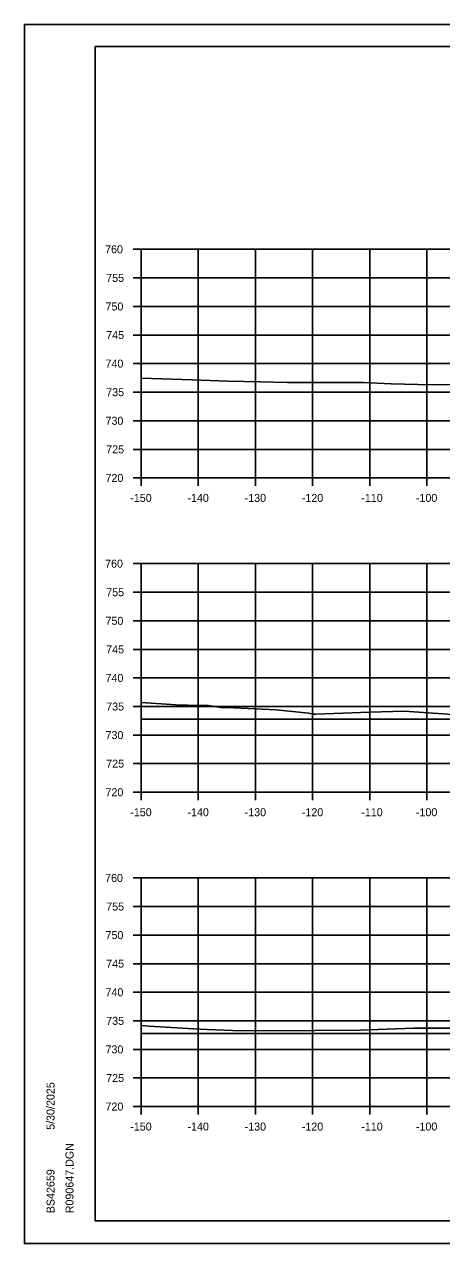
# Model space of a CAD drawing. Extents: x 1202951 to 1376887, y 378065 to 728038.
# Drawn here: x 1372926.7 to 1372999.7, y 380735.8 to 380949.1 of the extents above; entities that cross this region are included whole.
import ezdxf

# ---------------------------------------------------------------- set-up
doc = ezdxf.new("R2010")
doc.units = 0
for name, color, linetype in [('Default', 7, 'Continuous'), ('R_Axis', 7, 'Continuous'), ('R_Axis Annot', 7, 'Continuous'), ('R_Detour Annot', 7, 'Continuous'), ('R_Exist Surface', 7, 'Continuous'), ('R_Grid', 7, 'Continuous'), ('R_No Plot', 7, 'Continuous')]:
    doc.layers.add(name, color=color, linetype=linetype)

msp = doc.modelspace()

# ---------------------------------------------------------------- linework, layer by layer
at = {"layer": 'Default'}
msp.add_line((1372947.13, 380827.54), (1373247.13, 380827.54), dxfattribs=at)
at = {"layer": 'R_Axis'}
for p, q in [((1372945.73, 380909.74), (1372947.13, 380909.74)), ((1372947.13, 380869.74), (1372947.13, 380909.74)), ((1372945.73, 380904.74), (1372947.13, 380904.74)), ((1372945.73, 380899.74), (1372947.13, 380899.74)), ((1372945.73, 380894.74), (1372947.13, 380894.74)), ((1372945.73, 380889.74), (1372947.13, 380889.74)), ((1372945.73, 380884.74), (1372947.13, 380884.74)), ((1372945.73, 380879.74), (1372947.13, 380879.74)), ((1372945.73, 380874.74), (1372947.13, 380874.74)), ((1372945.73, 380869.74), (1372947.13, 380869.74)), ((1372947.13, 380869.74), (1373247.13, 380869.74)), ((1372947.13, 380868.34), (1372947.13, 380869.74)), ((1372957.13, 380868.34), (1372957.13, 380869.74)), ((1372967.13, 380868.34), (1372967.13, 380869.74)), ((1372977.13, 380868.34), (1372977.13, 380869.74)), ((1372987.13, 380868.34), (1372987.13, 380869.74)), ((1372997.13, 380868.34), (1372997.13, 380869.74)), ((1372945.73, 380854.74), (1372947.13, 380854.74)), ((1372947.13, 380814.74), (1372947.13, 380854.74)), ((1372945.73, 380849.74), (1372947.13, 380849.74)), ((1372945.73, 380844.74), (1372947.13, 380844.74)), ((1372945.73, 380839.74), (1372947.13, 380839.74)), ((1372945.73, 380834.74), (1372947.13, 380834.74)), ((1372945.73, 380829.74), (1372947.13, 380829.74)), ((1372945.73, 380824.74), (1372947.13, 380824.74)), ((1372945.73, 380819.74), (1372947.13, 380819.74)), ((1372945.73, 380814.74), (1372947.13, 380814.74)), ((1372947.13, 380814.74), (1373247.13, 380814.74)), ((1372947.13, 380813.34), (1372947.13, 380814.74)), ((1372957.13, 380813.34), (1372957.13, 380814.74)), ((1372967.13, 380813.34), (1372967.13, 380814.74)), ((1372977.13, 380813.34), (1372977.13, 380814.74)), ((1372987.13, 380813.34), (1372987.13, 380814.74)), ((1372997.13, 380813.34), (1372997.13, 380814.74)), ((1372945.73, 380799.74), (1372947.13, 380799.74)), ((1372947.13, 380759.74), (1372947.13, 380799.74)), ((1372945.73, 380794.74), (1372947.13, 380794.74)), ((1372945.73, 380789.74), (1372947.13, 380789.74)), ((1372945.73, 380784.74), (1372947.13, 380784.74)), ((1372945.73, 380779.74), (1372947.13, 380779.74)), ((1372945.73, 380774.74), (1372947.13, 380774.74)), ((1372945.73, 380769.74), (1372947.13, 380769.74)), ((1372945.73, 380764.74), (1372947.13, 380764.74)), ((1372945.73, 380759.74), (1372947.13, 380759.74)), ((1372947.13, 380759.74), (1373247.13, 380759.74)), ((1372947.13, 380758.34), (1372947.13, 380759.74)), ((1372957.13, 380758.34), (1372957.13, 380759.74)), ((1372967.13, 380758.34), (1372967.13, 380759.74)), ((1372977.13, 380758.34), (1372977.13, 380759.74)), ((1372987.13, 380758.34), (1372987.13, 380759.74)), ((1372997.13, 380758.34), (1372997.13, 380759.74))]:
    msp.add_line(p, q, dxfattribs=at)
at = {"layer": 'R_Detour Annot'}
msp.add_line((1372947.13, 380772.54), (1373004.99, 380772.54), dxfattribs=at)
at = {"layer": 'R_Exist Surface'}
for points in [[(1372947.13, 380887.19), (1372956.12, 380886.91), (1372962.26, 380886.65), (1372967.87, 380886.58), (1372972.71, 380886.46), (1372973.01, 380886.46), (1372975.18, 380886.46), (1372986.01, 380886.42), (1372990.89, 380886.23), (1372995.51, 380886.1), (1373007.53, 380886.01)], [(1372947.13, 380830.45), (1372953.29, 380830.02), (1372957.46, 380829.89), (1372958.55, 380829.98), (1372961.07, 380829.56), (1372963.42, 380829.51), (1372970.73, 380829.14), (1372976.48, 380828.56), (1372977.2, 380828.42), (1372977.67, 380828.42), (1372987.12, 380828.75), (1372993.15, 380828.93), (1373002.48, 380828.31)], [(1372947.13, 380773.9), (1372948.51, 380773.82), (1372949.49, 380773.75), (1372956.29, 380773.36), (1372958.71, 380773.2), (1372964.59, 380772.98), (1372977.51, 380773.04), (1372985.49, 380773.13), (1372994.85, 380773.48), (1373013.61, 380773.45)]]:
    msp.add_lwpolyline(points, dxfattribs=at)
at = {"layer": 'R_Grid'}
for p, q in [((1372947.13, 380909.74), (1373247.13, 380909.74)), ((1372947.13, 380869.74), (1372947.13, 380909.74)), ((1372957.13, 380869.74), (1372957.13, 380909.74)), ((1372967.13, 380869.74), (1372967.13, 380909.74)), ((1372977.13, 380869.74), (1372977.13, 380909.74)), ((1372987.13, 380869.74), (1372987.13, 380909.74)), ((1372997.13, 380869.74), (1372997.13, 380909.74)), ((1372947.13, 380904.74), (1373247.13, 380904.74)), ((1372947.13, 380899.74), (1373247.13, 380899.74)), ((1372947.13, 380894.74), (1373247.13, 380894.74)), ((1372947.13, 380889.74), (1373247.13, 380889.74)), ((1372947.13, 380884.74), (1373247.13, 380884.74)), ((1372947.13, 380879.74), (1373247.13, 380879.74)), ((1372947.13, 380874.74), (1373247.13, 380874.74)), ((1372947.13, 380869.74), (1373247.13, 380869.74)), ((1372947.13, 380854.74), (1373247.13, 380854.74)), ((1372947.13, 380814.74), (1372947.13, 380854.74)), ((1372957.13, 380814.74), (1372957.13, 380854.74)), ((1372967.13, 380814.74), (1372967.13, 380854.74)), ((1372977.13, 380814.74), (1372977.13, 380854.74)), ((1372987.13, 380814.74), (1372987.13, 380854.74)), ((1372997.13, 380814.74), (1372997.13, 380854.74)), ((1372947.13, 380849.74), (1373247.13, 380849.74)), ((1372947.13, 380844.74), (1373247.13, 380844.74)), ((1372947.13, 380839.74), (1373247.13, 380839.74)), ((1372947.13, 380834.74), (1373247.13, 380834.74)), ((1372947.13, 380829.74), (1373247.13, 380829.74)), ((1372947.13, 380824.74), (1373247.13, 380824.74)), ((1372947.13, 380819.74), (1373247.13, 380819.74)), ((1372947.13, 380814.74), (1373247.13, 380814.74)), ((1372947.13, 380799.74), (1373247.13, 380799.74)), ((1372947.13, 380759.74), (1372947.13, 380799.74)), ((1372957.13, 380759.74), (1372957.13, 380799.74)), ((1372967.13, 380759.74), (1372967.13, 380799.74)), ((1372977.13, 380759.74), (1372977.13, 380799.74)), ((1372987.13, 380759.74), (1372987.13, 380799.74)), ((1372997.13, 380759.74), (1372997.13, 380799.74)), ((1372947.13, 380794.74), (1373247.13, 380794.74)), ((1372947.13, 380789.74), (1373247.13, 380789.74)), ((1372947.13, 380784.74), (1373247.13, 380784.74)), ((1372947.13, 380779.74), (1373247.13, 380779.74)), ((1372947.13, 380774.74), (1373247.13, 380774.74)), ((1372947.13, 380769.74), (1373247.13, 380769.74)), ((1372947.13, 380764.74), (1373247.13, 380764.74)), ((1372947.13, 380759.74), (1373247.13, 380759.74))]:
    msp.add_line(p, q, dxfattribs=at)
at = {"layer": 'R_No Plot'}
for p, q in [((1372926.73, 380949.1), (1373260.07, 380949.1)), ((1372939.13, 380945.2), (1373255.31, 380945.2)), ((1372939.13, 380739.74), (1372939.13, 380945.2)), ((1372939.13, 380739.74), (1372939.13, 380739.74)), ((1373255.31, 380739.74), (1372939.13, 380739.74)), ((1372926.73, 380735.76), (1373260.07, 380735.76))]:
    msp.add_line(p, q, dxfattribs=at)
for points in [[(1372926.73, 380949.1), (1373260.07, 380949.1), (1373260.07, 380735.76), (1372926.73, 380735.76)], [(1373173.05, 380945.2), (1373192.67, 380945.2), (1373192.67, 380935.32), (1373208.79, 380935.32), (1373231.99, 380935.32), (1373231.99, 380910.99), (1373255.31, 380910.99), (1373255.31, 380739.74), (1372939.13, 380739.74), (1372939.13, 380945.2)]]:
    msp.add_lwpolyline(points, close=True, dxfattribs=at)

# ---------------------------------------------------------------- texts
at = {"layer": 'R_Axis Annot'}
for s, p in [('760', (1372940.84, 380909.04)), ('755', (1372941.03, 380904.04)), ('750', (1372940.91, 380899.04)), ('745', (1372941.03, 380894.04)), ('740', (1372940.91, 380889.04)), ('735', (1372941.03, 380884.04)), ('730', (1372940.91, 380879.04)), ('725', (1372941.03, 380874.04)), ('720', (1372940.91, 380869.04)), ('-150', (1372945.24, 380865.54)), ('-140', (1372955.24, 380865.54)), ('-130', (1372965.24, 380865.54)), ('-120', (1372975.24, 380865.54)), ('-110', (1372985.64, 380865.54)), ('-100', (1372995.19, 380865.54)), ('760', (1372940.84, 380854.04)), ('755', (1372941.03, 380849.04)), ('750', (1372940.91, 380844.04)), ('745', (1372941.03, 380839.04)), ('740', (1372940.91, 380834.04)), ('735', (1372941.03, 380829.04)), ('730', (1372940.91, 380824.04)), ('725', (1372941.03, 380819.04)), ('720', (1372940.91, 380814.04)), ('-150', (1372945.24, 380810.54)), ('-140', (1372955.24, 380810.54)), ('-130', (1372965.24, 380810.54)), ('-120', (1372975.24, 380810.54)), ('-110', (1372985.64, 380810.54)), ('-100', (1372995.19, 380810.54)), ('760', (1372940.84, 380799.04)), ('755', (1372941.03, 380794.04)), ('750', (1372940.91, 380789.04)), ('745', (1372941.03, 380784.04)), ('740', (1372940.91, 380779.04)), ('735', (1372941.03, 380774.04)), ('730', (1372940.91, 380769.04)), ('725', (1372941.03, 380764.04)), ('720', (1372940.91, 380759.04)), ('-150', (1372945.24, 380755.54)), ('-140', (1372955.24, 380755.54)), ('-130', (1372965.24, 380755.54)), ('-120', (1372975.24, 380755.54)), ('-110', (1372985.64, 380755.54)), ('-100', (1372995.19, 380755.54))]:
    msp.add_text(s, height=1.4, dxfattribs=at).set_placement(p)
at = {"layer": 'R_No Plot'}
for s, p in [('5/30/2025', (1372932, 380755.67)), ('R090647.DGN', (1372935.32, 380741.07)), ('BS42659', (1372932, 380741.07))]:
    msp.add_text(s, height=1.4, rotation=90, dxfattribs=at).set_placement(p)

doc.saveas('drawing.dxf')
